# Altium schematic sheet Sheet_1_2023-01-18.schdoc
size 176 x 171 mm
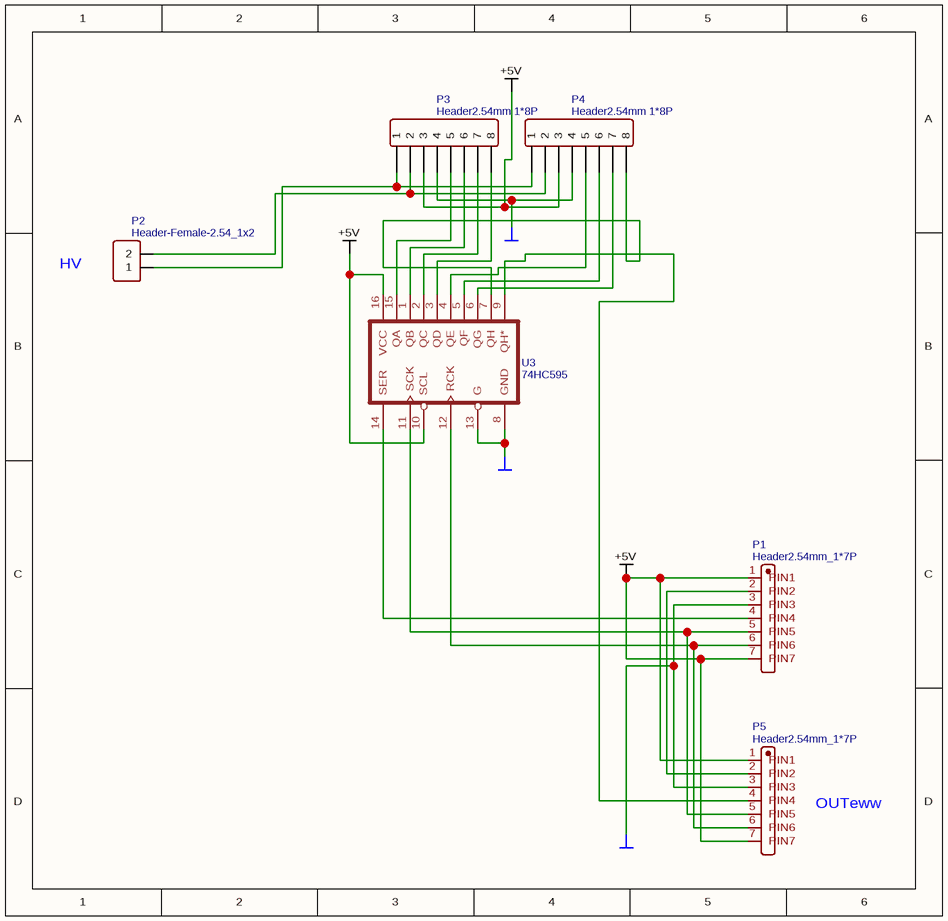
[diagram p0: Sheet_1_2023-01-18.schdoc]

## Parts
P1  Header2.54mm_1*7P  [HDR-7X1/2.54]
P2  Header-Female-2.54_1x2  [HDR-2X1/2.54]
P3  Header2.54mm 1*8P  [HDR-8X1/2.54]
P4  Header2.54mm 1*8P  [HDR-8X1/2.54]
P5  Header2.54mm_1*7P  [HDR-7X1/2.54]
U3  74HC595  [DIL16]

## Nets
+5V: P1.1(PIN1) P1.7(PIN7) P3.3 P4.3 P5.1(PIN1) P5.7(PIN7) U3.10(SCL) U3.16(VCC)
GND: P1.3(PIN3) P3.4 P4.4 P5.3(PIN3) U3.8(GND) U3.13(G)
NetP1_2: P1.2(PIN2) P5.2(PIN2)
NetP1_4: P1.4(PIN4) U3.14(SER)
NetP1_5: P1.5(PIN5) P5.5(PIN5) U3.11(SCK)
NetP1_6: P1.6(PIN6) P5.6(PIN6) U3.12(RCK)
NetP2_1: P2.1 P3.1 P4.1
NetP2_2: P2.2 P3.2 P4.2
NetP3_5: P3.5 U3.15(QA)
NetP3_6: P3.6 U3.1(QB)
NetP3_7: P3.7 U3.2(QC)
NetP3_8: P3.8 U3.3(QD)
NetP4_5: P4.5 U3.4(QE)
NetP4_6: P4.6 U3.5(QF)
NetP4_7: P4.7 U3.6(QG)
NetP4_8: P4.8 U3.7(QH)
NetP5_4: P5.4(PIN4) U3.9(QH*)

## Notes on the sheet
- HV
- OUTeww

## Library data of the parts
P1 P5 = Header2.54mm_1*7P: BOM_Manufacturer: ReliaPro; BOM_Manufacturer Part: Header2.54mm 1*7P
P2 = Header-Female-2.54_1x2: BOM_Manufacturer Part: Female header 1*2p; Contributor: milutzu
P3 P4 = Header2.54mm 1*8P: BOM_Manufacturer: ReliaPro
U3 = 74HC595: Contributor: SparkFun; sourceId: CIUtrpnzx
